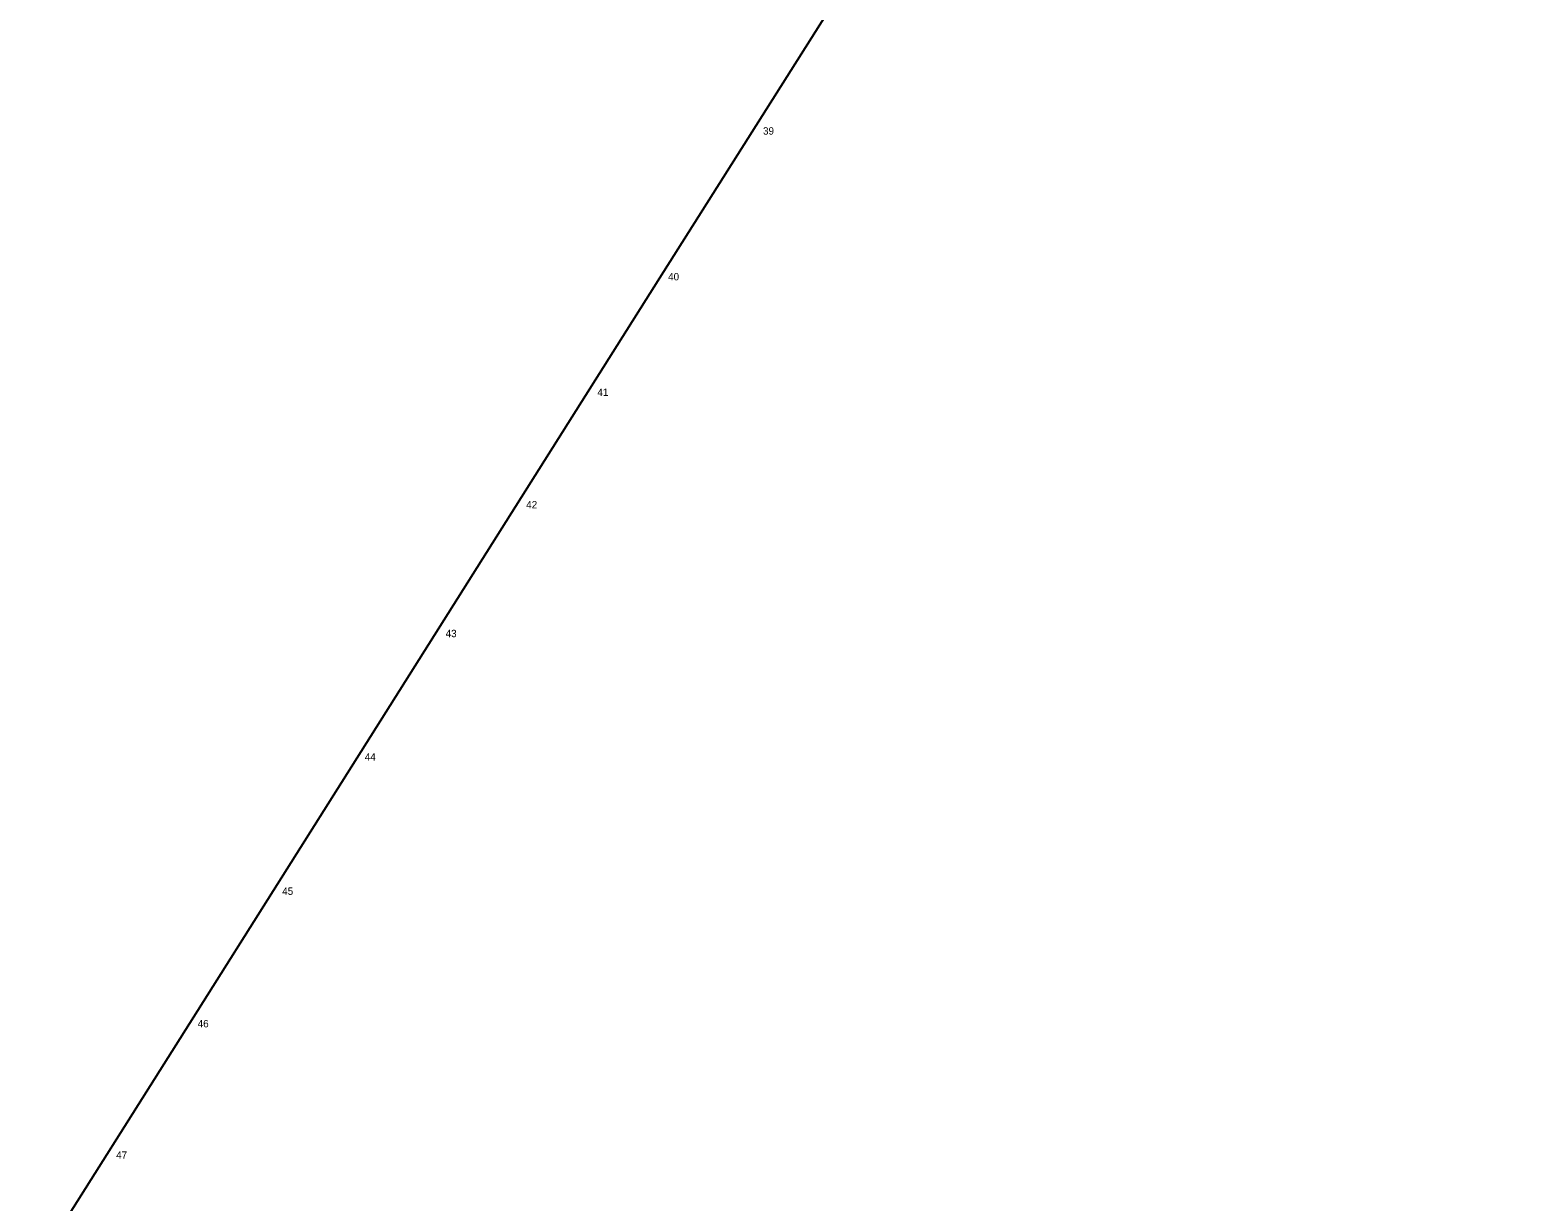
# Model space of a CAD drawing. Extents: x -743397 to -742769, y -1127804 to -1126284.
# Drawn here: x -743152.6 to -742909.3, y -1127047.4 to -1126856.5 of the extents above; entities that cross this region are included whole.
import ezdxf

# ---------------------------------------------------------------- set-up
doc = ezdxf.new("R2010")
doc.units = 0
for name, color, linetype in [('_Zabezpečovací zařízení_trasa', 7, 'Continuous'), ('křížky', 7, 'Continuous'), ('Vrstva 60', 7, 'Continuous')]:
    doc.layers.add(name, color=color, linetype=linetype)

# ---------------------------------------------------------------- blocks, each defined once
blk = doc.blocks.new('POINT_DISPLAY')
blk.add_line((0, 0), (0, 0))

msp = doc.modelspace()

# ---------------------------------------------------------------- linework, layer by layer
at = {"layer": '_Zabezpečovací zařízení_trasa'}
msp.add_lwpolyline([(-742909.33, -1126653.4), (-742919.08, -1126675.22), (-742929.03, -1126695.89), (-742939.4, -1126716.38), (-742952.25, -1126740.02), (-742965.82, -1126763.29), (-742978.53, -1126783.97), (-742991.5, -1126804.49), (-743018.82, -1126847.74), (-743049.28, -1126895.95), (-743072.49, -1126932.75), (-743098.65, -1126974.15), (-743125.94, -1127017.38), (-743152.6, -1127059.61)], dxfattribs=at)
at = {"layer": 'Vrstva 60'}
for p, q in [((-743034.05, -1126871.84), (-743034.05, -1126871.84)), ((-743049.28, -1126895.95), (-743049.28, -1126895.95)), ((-743060.88, -1126914.35), (-743060.88, -1126914.35)), ((-743072.49, -1126932.75), (-743072.49, -1126932.75)), ((-743085.57, -1126953.45), (-743085.57, -1126953.45)), ((-743098.65, -1126974.15), (-743098.65, -1126974.15)), ((-743112.29, -1126995.77), (-743112.29, -1126995.77)), ((-743125.94, -1127017.38), (-743125.94, -1127017.38)), ((-743139.27, -1127038.5), (-743139.27, -1127038.5))]:
    msp.add_line(p, q, dxfattribs=at)

# ---------------------------------------------------------------- block references
at = {"layer": 'křížky', "xscale": 10, "yscale": 10, "rotation": 61.14491455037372}
for p in [(-743034.05, -1126871.84), (-743049.28, -1126895.95), (-743060.88, -1126914.35), (-743072.49, -1126932.75), (-743085.57, -1126953.45), (-743098.65, -1126974.15), (-743112.29, -1126995.77), (-743125.94, -1127017.38), (-743139.27, -1127038.5)]:
    msp.add_blockref('POINT_DISPLAY', p, dxfattribs=at)

# ---------------------------------------------------------------- texts
at = {"layer": 'Vrstva 60'}
for s, p in [('39', (-743033.08, -1126873.61)), ('40', (-743048.55, -1126897.36)), ('41', (-743060.08, -1126916.18)), ('42', (-743071.68, -1126934.49)), ('43', (-743084.82, -1126955.48)), ('44', (-743098, -1126975.59)), ('45', (-743111.46, -1126997.46)), ('46', (-743125.24, -1127019.04)), ('47', (-743138.54, -1127040.46))]:
    msp.add_text(s, height=1.2, dxfattribs=at).set_placement(p)

doc.saveas('drawing.dxf')
